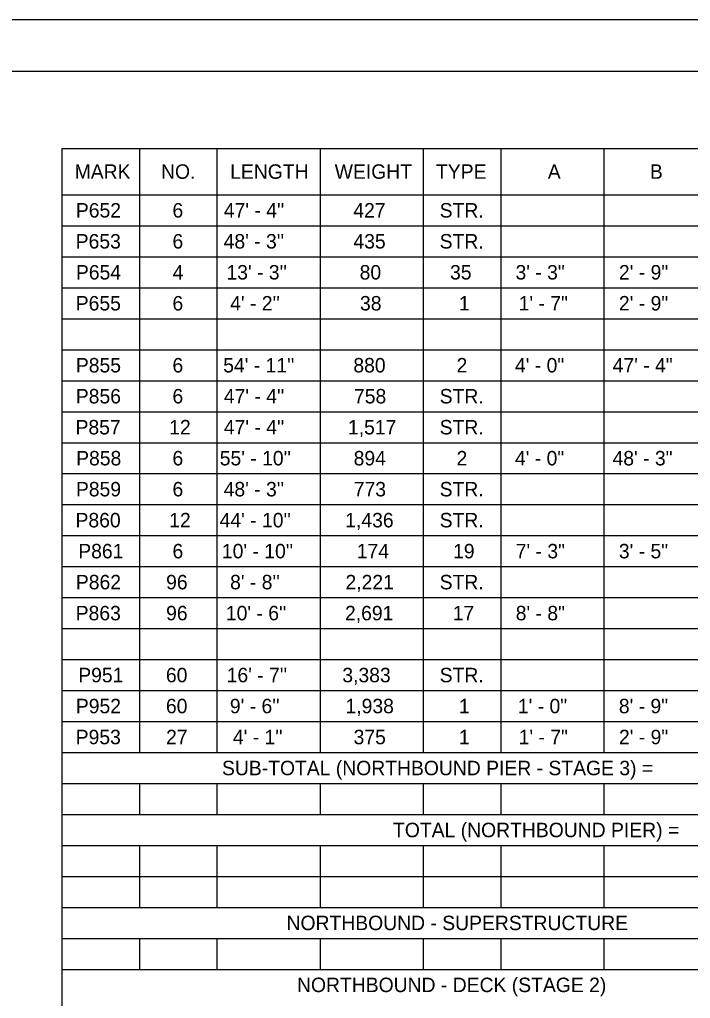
# Model space of a CAD drawing. Extents: x 1485751 to 1485785, y 230696.6 to 230718.6.
# Drawn here: x 1485773.25 to 1485779.75, y 230709.16 to 230718.64 of the extents above; entities that cross this region are included whole.
import ezdxf

# ---------------------------------------------------------------- set-up
doc = ezdxf.new("R2010")
doc.units = 0
for name, color, linetype in [('SH_Border', 7, 'Continuous'), ('SH_Cut_Line', 7, 'Continuous'), ('TX_P_Misc', 7, 'Continuous')]:
    doc.layers.add(name, color=color, linetype=linetype)

msp = doc.modelspace()

# ---------------------------------------------------------------- linework, layer by layer
at = {"layer": 'SH_Border'}
msp.add_lwpolyline([(1485753.0329, 230718.1408), (1485784.5329, 230718.1408), (1485784.5329, 230697.1408), (1485753.0329, 230697.1408)], close=True, dxfattribs=at)
at = {"layer": 'SH_Cut_Line'}
msp.add_lwpolyline([(1485751.0329, 230718.6408), (1485785.0329, 230718.6408), (1485785.0329, 230696.6408), (1485751.0329, 230696.6408)], close=True, dxfattribs=at)
at = {"layer": 'TX_P_Misc'}
for p, q in [((1485773.6579, 230717.394), (1485782.9079, 230717.394)), ((1485773.6579, 230717.394), (1485773.6579, 230699.244)), ((1485774.4079, 230717.394), (1485774.4079, 230711.544)), ((1485775.1579, 230717.394), (1485775.1579, 230711.544)), ((1485776.1579, 230717.394), (1485776.1579, 230711.544)), ((1485777.1579, 230717.394), (1485777.1579, 230711.544)), ((1485777.9079, 230717.394), (1485777.9079, 230711.544)), ((1485778.9079, 230717.394), (1485778.9079, 230711.544)), ((1485773.6579, 230716.944), (1485782.9079, 230716.944)), ((1485773.6579, 230716.644), (1485782.9079, 230716.644)), ((1485773.6579, 230716.344), (1485782.9079, 230716.344)), ((1485773.6579, 230716.044), (1485782.9079, 230716.044)), ((1485773.6579, 230715.744), (1485782.9079, 230715.744)), ((1485773.6579, 230715.444), (1485782.9079, 230715.444)), ((1485773.6579, 230715.144), (1485782.9079, 230715.144)), ((1485773.6579, 230714.844), (1485782.9079, 230714.844)), ((1485773.6579, 230714.544), (1485782.9079, 230714.544)), ((1485773.6579, 230714.244), (1485782.9079, 230714.244)), ((1485773.6579, 230713.944), (1485782.9079, 230713.944)), ((1485773.6579, 230713.644), (1485782.9079, 230713.644)), ((1485773.6579, 230713.344), (1485782.9079, 230713.344)), ((1485773.6579, 230713.044), (1485782.9079, 230713.044)), ((1485773.6579, 230712.744), (1485782.9079, 230712.744)), ((1485773.6579, 230712.444), (1485782.9079, 230712.444)), ((1485773.6579, 230712.144), (1485782.9079, 230712.144)), ((1485773.6579, 230711.844), (1485782.9079, 230711.844)), ((1485773.6579, 230711.544), (1485782.9079, 230711.544)), ((1485773.6579, 230711.244), (1485782.9079, 230711.244)), ((1485774.4079, 230711.244), (1485774.4079, 230710.944)), ((1485775.1579, 230711.244), (1485775.1579, 230710.944)), ((1485776.1579, 230711.244), (1485776.1579, 230710.944)), ((1485777.1579, 230711.244), (1485777.1579, 230710.944)), ((1485777.9079, 230711.244), (1485777.9079, 230710.944)), ((1485778.9079, 230711.244), (1485778.9079, 230710.944)), ((1485773.6579, 230710.944), (1485782.9079, 230710.944)), ((1485773.6579, 230710.644), (1485782.9079, 230710.644)), ((1485774.4079, 230710.644), (1485774.4079, 230710.044)), ((1485775.1579, 230710.644), (1485775.1579, 230710.044)), ((1485776.1579, 230710.644), (1485776.1579, 230710.044)), ((1485777.1579, 230710.644), (1485777.1579, 230710.044)), ((1485777.9079, 230710.644), (1485777.9079, 230710.044)), ((1485778.9079, 230710.644), (1485778.9079, 230710.044)), ((1485773.6579, 230710.344), (1485782.9079, 230710.344)), ((1485773.6579, 230710.044), (1485782.9079, 230710.044)), ((1485773.6579, 230709.744), (1485782.9079, 230709.744)), ((1485774.4079, 230709.744), (1485774.4079, 230709.444)), ((1485775.1579, 230709.744), (1485775.1579, 230709.444)), ((1485776.1579, 230709.744), (1485776.1579, 230709.444)), ((1485777.1579, 230709.744), (1485777.1579, 230709.444)), ((1485777.9079, 230709.744), (1485777.9079, 230709.444)), ((1485778.9079, 230709.744), (1485778.9079, 230709.444)), ((1485773.6579, 230709.444), (1485782.9079, 230709.444))]:
    msp.add_line(p, q, dxfattribs=at)

# ---------------------------------------------------------------- texts
for s, p in [('MARK', (1485773.7815, 230717.099)), ('NO.', (1485774.6181, 230717.099)), ('LENGTH', (1485775.2875, 230717.099)), ('WEIGHT', (1485776.3002, 230717.099)), ('TYPE', (1485777.2815, 230717.099)), ('A', (1485778.3643, 230717.099)), ('B', (1485779.3533, 230717.099)), ('P652', (1485773.7931, 230716.724)), ('6', (1485774.7288, 230716.724)), ("47' - 4''", (1485775.2263, 230716.724)), ('427', (1485776.4804, 230716.724)), ('STR.', (1485777.3168, 230716.724)), ('P653', (1485773.7915, 230716.424)), ('6', (1485774.7288, 230716.424)), ("48' - 3''", (1485775.2247, 230716.424)), ('435', (1485776.4815, 230716.424)), ('STR.', (1485777.3168, 230716.424)), ('P654', (1485773.7937, 230716.124)), ('4', (1485774.731, 230716.124)), ("13' - 3''", (1485775.2517, 230716.124)), ('80', (1485776.5416, 230716.124)), ('35', (1485777.4177, 230716.124)), ('3\' - 3"', (1485778.0513, 230716.124)), ('2\' - 9"', (1485779.0535, 230716.124)), ('P655', (1485773.792, 230715.824)), ('6', (1485774.7288, 230715.824)), ("4' - 2''", (1485775.2875, 230715.824)), ('38', (1485776.5454, 230715.824)), ('1', (1485777.5037, 230715.824)), ('1\' - 7"', (1485778.0822, 230715.824)), ('2\' - 9"', (1485779.0535, 230715.824)), ('P855', (1485773.7931, 230715.224)), ('6', (1485774.7288, 230715.224)), ("54' - 11''", (1485775.2203, 230715.224)), ('880', (1485776.4809, 230715.224)), ('2', (1485777.4805, 230715.224)), ('4\' - 0"', (1485778.0463, 230715.224)), ('47\' - 4"', (1485778.9929, 230715.224)), ('P856', (1485773.7926, 230714.924)), ('6', (1485774.7288, 230714.924)), ("47' - 4''", (1485775.2263, 230714.924)), ('758', (1485776.487, 230714.924)), ('STR.', (1485777.3168, 230714.924)), ('P857', (1485773.7898, 230714.624)), ('12', (1485774.6975, 230714.624)), ("47' - 4''", (1485775.2263, 230714.624)), ('1,517', (1485776.4287, 230714.624)), ('STR.', (1485777.3168, 230714.624)), ('P858', (1485773.7959, 230714.324)), ('6', (1485774.7288, 230714.324)), ("55' - 10''", (1485775.1867, 230714.324)), ('894', (1485776.4837, 230714.324)), ('2', (1485777.4805, 230714.324)), ('4\' - 0"', (1485778.0463, 230714.324)), ('48\' - 3"', (1485778.9912, 230714.324)), ('P859', (1485773.7937, 230714.024)), ('6', (1485774.7288, 230714.024)), ("48' - 3''", (1485775.2247, 230714.024)), ('773', (1485776.4848, 230714.024)), ('STR.', (1485777.3168, 230714.024)), ('P860', (1485773.7898, 230713.724)), ('12', (1485774.6975, 230713.724)), ("44' - 10''", (1485775.1856, 230713.724)), ('1,436', (1485776.4022, 230713.724)), ('STR.', (1485777.3168, 230713.724)), ('P861', (1485773.8164, 230713.424)), ('6', (1485774.7288, 230713.424)), ("10' - 10''", (1485775.2077, 230713.424)), ('174', (1485776.5135, 230713.424)), ('19', (1485777.4469, 230713.424)), ('7\' - 3"', (1485778.0535, 230713.424)), ('3\' - 5"', (1485779.0524, 230713.424)), ('P862', (1485773.7931, 230713.124)), ('96', (1485774.6671, 230713.124)), ("8' - 8''", (1485775.287, 230713.124)), ('2,221', (1485776.4044, 230713.124)), ('STR.', (1485777.3168, 230713.124)), ('P863', (1485773.7915, 230712.824)), ('96', (1485774.6671, 230712.824)), ("10' - 6''", (1485775.2462, 230712.824)), ('2,691', (1485776.4, 230712.824)), ('17', (1485777.4431, 230712.824)), ('8\' - 8"', (1485778.0535, 230712.824)), ('P951', (1485773.8164, 230712.224)), ('60', (1485774.6655, 230712.224)), ("16' - 7''", (1485775.2539, 230712.224)), ('3,383', (1485776.374, 230712.224)), ('STR.', (1485777.3168, 230712.224)), ('P952', (1485773.7931, 230711.924)), ('60', (1485774.6655, 230711.924)), ("9' - 6''", (1485775.2847, 230711.924)), ('1,938', (1485776.4049, 230711.924)), ('1', (1485777.5037, 230711.924)), ('1\' - 0"', (1485778.0745, 230711.924)), ('8\' - 9"', (1485779.0524, 230711.924)), ('P953', (1485773.7915, 230711.624)), ('27', (1485774.6666, 230711.624)), ("4' - 1''", (1485775.314, 230711.624)), ('375', (1485776.4831, 230711.624)), ('1', (1485777.5037, 230711.624)), ('1\' - 7"', (1485778.0822, 230711.624)), ('2\' - 9"', (1485779.0535, 230711.624)), ('SUB-TOTAL (NORTHBOUND PIER - STAGE 3) =', (1485775.2084, 230711.324)), ('TOTAL (NORTHBOUND PIER) =', (1485776.8651, 230710.724)), ('NORTHBOUND - SUPERSTRUCTURE', (1485775.8337, 230709.824)), ('NORTHBOUND - DECK (STAGE 2)', (1485775.9352, 230709.224))]:
    msp.add_text(s, height=0.14, dxfattribs=at).set_placement(p)

doc.saveas('drawing.dxf')
